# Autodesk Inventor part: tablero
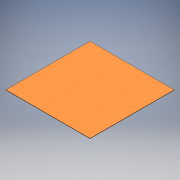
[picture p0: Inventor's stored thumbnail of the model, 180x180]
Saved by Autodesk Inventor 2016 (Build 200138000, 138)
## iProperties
Created: 2016-06
Part Number: tablero
Material: Genérico
Document SubType Name: Modeling
Designer: adm
Density: 1 g/cm^3
Appearance: Valor por defecto
Author: adm
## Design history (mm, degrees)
sketch "Boceto1"
  geometry: L1 (-400, -400)-(400, -400); L2 (400, -400)-(400, 400); L3 (400, 400)-(-400, 400); L4 (-400, 400)-(-400, -400); L5 (-400, -400)-(400, 400); L6 (400, -400)-(-400, 400); 1 further point
  constraints: 12 end point, 2 midpoint, 2 parallel, 1 horizontal, 1 perpendicular
  dimensions: "d0" = 800 distance of L3.end L2.end; "d1" = 800 distance of L2.end L1.end
extrude "Extrusión1" new body sketch "Boceto1" distance "d2" = 4; taper "d3" = 0 deg
node "Sólido1"
